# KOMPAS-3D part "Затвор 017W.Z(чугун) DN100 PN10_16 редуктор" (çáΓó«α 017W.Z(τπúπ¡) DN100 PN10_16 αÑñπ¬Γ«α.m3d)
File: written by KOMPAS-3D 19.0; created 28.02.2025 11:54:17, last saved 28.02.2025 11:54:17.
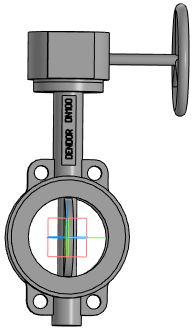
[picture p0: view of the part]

Document properties: Автор: Евгений; Полное имя файла: Затвор 017W.Z(чугун) DN100 PN10_16 редуктор.a3d

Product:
- Part/product: Затвор 017W.Z(чугун) DN100 PN10_16 редуктор
    Масса: 13.5946

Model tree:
1. Операция без истории:1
